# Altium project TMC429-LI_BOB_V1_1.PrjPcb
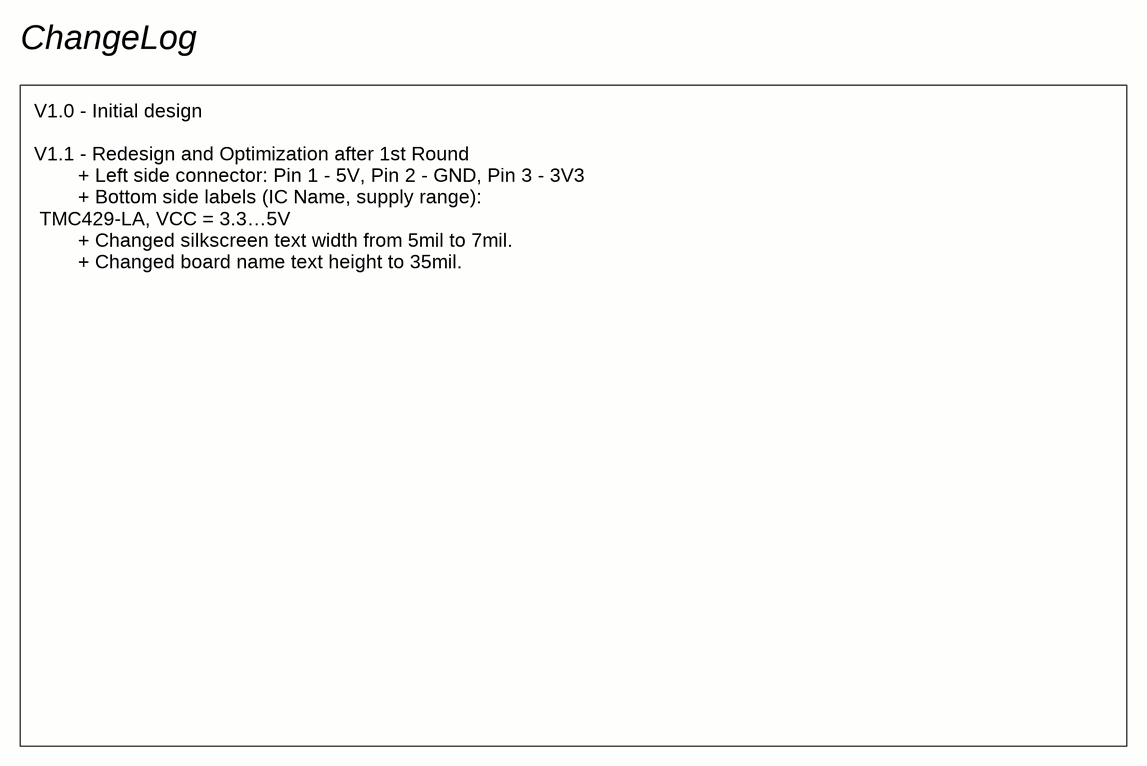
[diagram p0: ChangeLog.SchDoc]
BoardName: TMC429-LA_BOB; BoardVersion: 1.1; Chip: TMC429-LA; VCC: 3.3...5V
2 sheets, 31 parts. Net scope: global (net labels, ports and power ports of the same name join across sheets).
Board file: TMC429-LI_BOB_V1_1.PcbDoc
Sheets:
  ChangeLog.SchDoc
  TMC429-LI_BOB_V1_1.SchDoc

## Sheet ChangeLog.SchDoc
size A4

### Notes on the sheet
- ChangeLog
- V1.0 - Initial design
  V1.1 - Redesign and Optimization after 1st Round
  + Left side connector: Pin 1 - 5V, Pin 2 - GND, Pin 3 - 3V3
  + Bottom side labels (IC Name, supply range):
  TMC429-LA, VCC = 3.3…5V
  + Changed silkscreen text width from 5mil to 7mil.
  + Changed board name text height to 35mil.

## Sheet TMC429-LI_BOB_V1_1.SchDoc
size A4
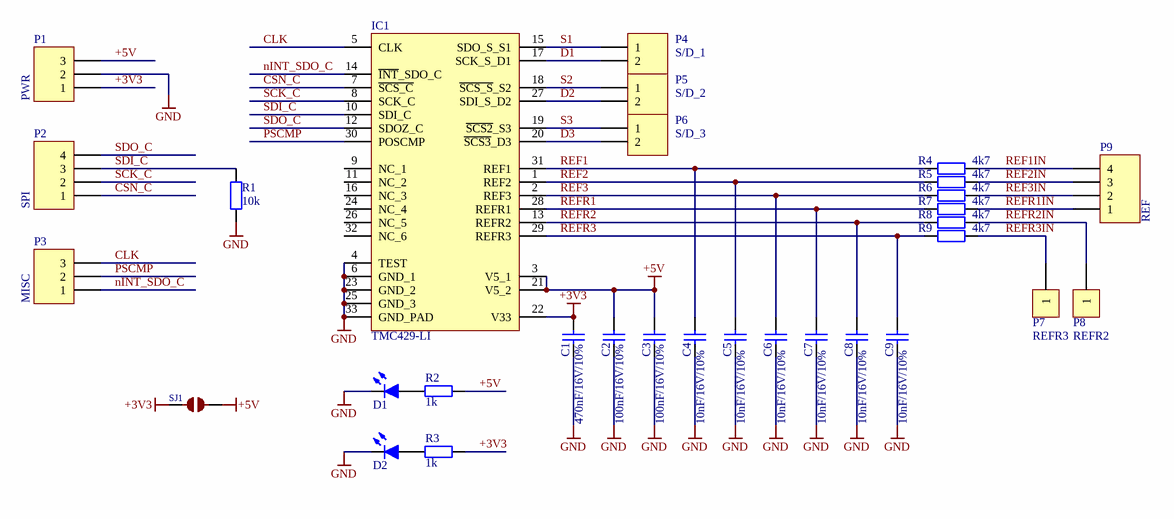
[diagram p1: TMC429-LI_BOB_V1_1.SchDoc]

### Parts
C1  470nF/16V/10%  [C0603]
C2  100nF/16V/10%  [C0603]
C3  100nF/16V/10%  [C0603]
C4  10nF/16V/10%  [C0603]
C5  10nF/16V/10%  [C0603]
C6  10nF/16V/10%  [C0603]
C7  10nF/16V/10%  [C0603]
C8  10nF/16V/10%  [C0603]
C9  10nF/16V/10%  [C0603]
D1  LED, Blue, SMD, 20mA, 2.8V, 465 nm  [LED_0603]  (value not drawn)
D2  LED, Blue, SMD, 20mA, 2.8V, 465 nm  [LED_0603]  (value not drawn)
IC1  TMC429-LI  [TMC429_QFN32_0.5_5.0X5.0]
P1  PWR  [3_PIN_THT]
P2  SPI  [4_PIN_THT]
P3  MISC  [3_PIN_THT]
P4  S/D_1  [2_PIN_THT]
P5  S/D_2  [2_PIN_THT]
P6  S/D_3  [2_PIN_THT]
P7  REFR3  [TH_PIN]
P8  REFR2  [TH_PIN]
P9  REF  [4_PIN_THT]
R1  10k  [R0603]
R2  1k  [R0603]
R3  1k  [R0603]
R4  4k7  [R0603]
R5  4k7  [R0603]
R6  4k7  [R0603]
R7  4k7  [R0603]
R8  4k7  [R0603]
R9  4k7  [R0603]
SJ1  SPI_MODE  [SJ_SMALL_2PIN_1x0.635]  (value not drawn)

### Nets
+3V3: C1.1 IC1.22(V33) P1.1 R3.2 SJ1.1
+5V: C2.1 C3.1 IC1.3(V5_1) IC1.21(V5_2) P1.3 R2.2 SJ1.2
GND: C1.2 C2.2 C3.2 C4.2 C5.2 C6.2 C7.2 C8.2 C9.2 D1.2(K) D2.2(K) IC1.4(TEST) IC1.6(GND_1) IC1.23(GND_2) IC1.25(GND_3) IC1.33(GND_PAD) P1.2 R1.2
CLK: IC1.5(CLK) P3.3
CSN_C: IC1.7(~{SCS_C}) P2.1
D1: IC1.17(SCK_S_D1) P4.2
D2: IC1.27(SDI_S_D2) P5.2
D3: IC1.20(~{SCS3}_D3) P6.2
nINT_SDO_C: IC1.14(~{INT}_SDO_C) P3.1
PSCMP: IC1.30(POSCMP) P3.2
REF1: C4.1 IC1.31(REF1) R4.2
REF1IN: P9.4 R4.1
REF2: C5.1 IC1.1(REF2) R5.2
REF2IN: P9.3 R5.1
REF3: C6.1 IC1.2(REF3) R6.2
REF3IN: P9.2 R6.1
REFR1: C7.1 IC1.28(REFR1) R7.2
REFR1IN: P9.1 R7.1
REFR2: C8.1 IC1.13(REFR2) R8.2
REFR2IN: P8.1 R8.1
REFR3: C9.1 IC1.29(REFR3) R9.2
REFR3IN: P7.1 R9.1
S1: IC1.15(SDO_S_S1) P4.1
S2: IC1.18(~{SCS_S}_S2) P5.1
S3: IC1.19(~{SCS2}_S3) P6.1
SCK_C: IC1.8(SCK_C) P2.2
SDI_C: IC1.10(SDI_C) P2.3 R1.1
SDO_C: IC1.12(SDOZ_C) P2.4
NetD1_1: D1.1(A) R2.1
NetD2_1: D2.1(A) R3.1

Not connected (* = marked no-connect by the designer): IC1 9(NC_1) 11(NC_2) 16(NC_3) 24(NC_4) 26(NC_5) 32(NC_6)

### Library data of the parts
C1 = Capacitor: Ceramic capacitor; MPN: MC0603X474K160CT; Type: MLCC; VoltageRating: 16V; ComponentLinknDescription: Datasheet; MF: Multicomp; Capacitance: 470nF; Precision: 10%
C2 C3 = Capacitor: Ceramic capacitor; MPN: MC0603B104K160CT; Type: MLCC; VoltageRating: 16V; ComponentLinknDescription: Datasheet; MF: Multicomp; Capacitance: 100nF; Precision: 10%
C4-C9 = Capacitor: Ceramic capacitor; MPN: MC0603B103K160CT; Type: MLCC; VoltageRating: 16V; ComponentLinknDescription: Datasheet; MF: Multicomp; Capacitance: 10nF; Precision: 10%
D1 D2 = LED, Blue, SMD, 20mA, 2.8V, 465 nm: MPN: LTST-C191TBKT-5A; MF: Lite-On
IC1 = TMC429-LI: Intelligent Triple Stepper Motor Controller with SPI, Step/Dir, QFN32(5x5); Geometry.Height: 0,9mm; MF: TRINAMIC; Ordercode - Distri#1: 1460-1071-1-ND; Ordercode - Distri#2: 1858310
P1 P3 = Header 3: Header, 3-Pin; Fitted: Not fitted
P2 P9 = Header 4: Header, 4-Pin; Fitted: Not fitted
P4-P6 = Header 2: Header, 2-Pin; Fitted: Not fitted
P7 P8 = PIN: Note: n.b; Fitted: Not fitted
R1 = 10 kohm, 50 V, 0603 [1608 Metric], 63 mW, ± 1%, MC Series: MPN: MC0063W0603110K; VoltageRating: 50V; Temp coefficient: *ppm; PowerRating: 63mW; MF: MULTICOMP
R2 R3 = 1 kohm, 50 V, 0603 [1608 Metric], 63 mW, ± 1%, MC Series: MPN: MC0063W060311K; VoltageRating: 50V; Temp coefficient: *ppm; PowerRating: 63mW; MF: MULTICOMP
R4-R9 = 4.7 kohm, 50 V, 0603 [1608 Metric], 63 mW, ± 1%, MC Series: MPN: MC0063W060314K7; VoltageRating: 50V; Temp coefficient: *ppm; PowerRating: 63mW; MF: MULTICOMP
SJ1 = SJ: SMD solder <b>JUMPER</b>; Fitted: Not fitted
